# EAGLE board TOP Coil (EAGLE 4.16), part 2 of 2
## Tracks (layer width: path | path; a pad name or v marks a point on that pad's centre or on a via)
+1.2V  (via drill 0.51)
  Top 0.178: v160.66,116.84 160.34,116.52 159.54,116.52 IC9.37 158.27,116.52 155.1,116.52 154.15,117.47 152.72,117.47 | v156.84,113.03 156.69,113.35 156.69,114.14 IC9.35 | IC9.26 152.24,115.41 152.24,115.89 v152.4,116.39 152.56,116.52 152.56,117.32 152.72,117.47 | 157.53,122.98 156.21,124.3 156.21,126.68 156.37,126.84 157.16,126.84 v157.48,127 157.16,127.32 157.16,128.59 v157.35,128.91 157.8,129.06 158.27,129.06 IC9.62 | IC16.2 v107.31,95.09 107.31,96.2 107.31,96.21 | v140.21,137.35 140.18,136.84 140.18,136.53 IC9.107 | IC9.81 153.19,135.1 153.19,134.3 v153.03,133.99 152.72,133.67 152.72,132.87 145.89,126.05 144.15,126.05 | v139.7,126.36 139.38,126.52 138.59,126.52 IC9.124 | 141.1,126.05 141.1,123.79 140.81,123.51 140.02,123.51 v139.7,123.19 139.38,123.03 138.59,123.03 IC9.131 137.32,123.03 136.05,123.03 127,113.98 v127,113.35 | 141.1,126.05 144.15,126.05 | 141.1,126.05 141.1,126.11 | 141.1,126.11 141.1,132.78 139.89,133.99 138.59,133.99 IC9.109 136.46,134.06 v136.02,134.49 | 144.15,126.05 152.72,117.47 | v157.23,122.56 157.73,123.06 158.87,123.06 158.88,123.06 IC9.50 | v141.43,126.34 141.2,126.11 141.1,126.11
  Bottom 0.178: v160.66,116.84 159.7,116.84 C58.2 159.26,116.71 159.26,114.47 C52.2 156.69,113.98 156.69,113.35 v156.84,113.03 | C54.2 152.4,115.57 v152.4,116.39 152.72,116.52 152.72,119.03 157.19,123.51 | v157.35,128.91 158.12,128.91 C48.2 | 157.19,123.51 158.12,123.51 C51.2 157.86,123.06 v157.23,122.56 | 157.19,123.51 156.21,124.49 156.21,126.68 156.37,126.84 157.16,126.84 v157.48,127 | v140.21,137.35 C53.2 139.86,135.57 138.43,135.57 137.79,134.94 137.79,134.14 C50.2 136.56,134.49 v136.02,134.49 | v153.03,133.99 153.03,134.94 C49.2 | v139.7,123.19 138.75,123.19 C56.2 | C57.2 138.75,126.36 v139.7,126.36 141.48,126.36 v141.43,126.34 | v107.31,95.09 108.74,95.09 v127,113.35
  pour Top (isolate 0.203): 100.97,125.09 100.97,95.89 116.2,95.89 116.2,125.09
+3.3V  (via drill 0.51)
  Top 0.178: C3.1 IC1.27 124.14,34.45 124.94,34.45 128.59,38.1 128.59,62.55 132.4,66.36 132.4,69.37 132.56,69.53 133.35,69.53 C63.1 133.67,70.17 133.67,71.6 IC11.27 133.83,73.66 v133.83,75.41 | C64.1 IC12.27 v129.54,189.23 | C19.1 IC4.27 v119.22,157.48 119.54,157.8 v122.24,160.5 | SW1.10 SW1.9 SW1.8 SW1.7 | SW1.7 SW1.6 | IC9.66 158.27,130.97 157.67,130.97 v157.29,130.81 157.04,130.49 156.37,130.49 155.26,129.38 155.26,121.44 156.05,120.65 157.16,120.65 157.42,120.84 v157.29,120.71 157.8,121.13 158.27,121.13 IC9.46 159.54,121.13 162.37,121.13 162.53,121.28 162.53,124.94 162.37,125.09 159.54,125.09 IC9.54 158.27,125.09 v157.29,125.09 | IC9.77 155.26,135.1 155.26,134.3 v154.94,133.99 | v151.76,133.99 151.61,134.3 151.61,135.1 IC9.84 | v139.46,131.13 138.98,130.49 138.59,130.49 IC9.116 | IC9.102 142.72,135.1 142.72,134.81 v143.13,134.24 | v146.05,133.99 146.21,134.3 146.21,135.1 IC9.95 146.21,136.53 146.21,141.29 145.61,141.89 145.61,146.4 146.05,146.84 146.05,151.45 SW1.7 | v150.5,116.39 150.65,115.89 150.65,115.41 IC9.23 150.65,114.14 150.65,113.19 v147.96,110.49 | v153.67,116.39 153.67,115.41 IC9.29 | IC9.5 141.6,115.41 v141.6,116.84 141.6,117.32 139.38,119.54 138.59,119.54 IC9.138 | R54.2 92.87,87 92.87,88.42 92.55,88.42 IC15.2 92.08,96.2 92.08,96.21 | v139.7,125.09 138.59,125.09 IC9.127 | v99.69,96.68 98.9,96.68 C85.2
  Bottom 0.178: v129.54,189.23 129.54,178.44 119.22,168.12 v119.22,157.48 | v157.29,130.81 158.12,130.81 C44.2 158.12,131.44 158.12,133.83 156.37,135.57 | R35.1B 154.46,138.75 154.46,139.06 R35.2B 154.43,139.32 155.92,139.32 156.53,138.72 156.53,135.73 156.37,135.57 | 156.37,135.57 155.57,135.57 C43.2 154.94,134.94 v154.94,133.99 154.62,133.67 154.62,132.87 154.46,132.72 152.08,132.72 151.92,132.87 151.92,133.67 v151.76,133.99 151.76,134.94 C42.2 151.29,135.41 146.53,135.41 C33.2 | C40.2 138.75,130.81 v139.46,131.13 139.81,130.49 142.88,130.49 143.6,131.22 143.6,133.92 v143.13,134.24 142.88,134.94 C41.2 143.03,135.41 145.73,135.41 C33.2 | v146.05,133.99 146.05,134.94 C33.2 | v150.5,116.39 150.5,115.57 C38.2 150.97,114.62 151.29,114.3 152.88,114.3 153.19,114.62 C36.2 v153.67,116.39 153.99,116.52 153.99,117.32 157.07,120.4 157.07,120.49 v157.29,120.71 158.12,121.28 C34.2 | v157.29,125.09 C45.2 | 147.64,110.17 142.88,114.94 142.08,114.94 C39.2 141.6,115.57 v141.6,116.84 141.45,117.16 141.45,119.86 140.65,120.65 | 147.64,110.17 148.91,108.9 148.91,106.68 R31.2B 148.99,105.81 148.18,105 148.19,105 R31.3A | 147.64,110.17 v147.96,110.49 | C46.2 138.75,125.09 v139.7,125.09 140.02,124.78 140.81,124.78 140.97,124.62 140.97,120.97 140.65,120.65 | 140.65,120.65 139.86,119.86 138.75,119.86 C47.2 137.79,119.22 137.79,118.11 137.64,117.95 137,117.95 C35.1 136.05,117.63 135.1,117.63 IC8.4 132.87,116.68 132.24,116.68 131.13,115.57 | v99.69,96.68 109.22,96.68 128.11,115.57 131.13,115.57 | 131.13,115.57 131.13,112.87 135.89,108.11 136.84,108.11 IC7.3 138.75,107.79 140.02,107.79 141.13,106.68 IC7.7 IC7.8 143.13,105.41 143.99,104.55
  Bottom 0.178: v122.24,160.5 127.16,160.5 127.95,161.29 129.54,161.29 137.79,153.03 138.43,153.03 SW1.10 | v133.83,75.41 140.97,82.55 140.97,93.82 145.41,98.27 J3.4 144.78,100.01 143.99,100.81 143.99,104.55 | C37.1 145.16,104.52 144.02,104.52 143.99,104.55
  pour Top (isolate 0.203): 98.42,95.89 98.42,125.09 83.19,125.09 83.19,95.89
+5V  (via drill 0.51)
  Top 0.178: R48.2 120.65,14.45 120.65,15.72 Q6.3 | IC1.24 C1.2 120.97,37.62 120.97,36.99 119.54,35.56 118.9,35.56 | 118.9,35.56 115.73,32.38 115.73,24.29 | 115.73,24.29 115.73,23.65 115.57,23.5 R44.2 | 115.73,24.29 120.65,19.37 120.65,17.3 Q6.3 | AUD1.+ 143.67,6.35 136.37,6.35 126.84,15.88 121.92,15.88 Q6.3 | C74.2 IC14.5 | C61.2 IC12.24 133.35,189.39 130.02,186.06 119.86,186.06 C74.2 | C17.2 v115.73,161.29 IC4.24 | IC5.8 C22.2 100.81,177.16 v102.08,177.16 | v106.05,173.51 118.27,185.74 118.9,185.74 C74.2 | C55.1 160.66,91.6 IC10.14 160.34,88.58 160.34,87.31 155.57,82.55 138.59,82.55 130.49,74.45 130.02,74.45 | C59.2 129.86,70.17 129.86,71.6 IC11.24 130.02,73.66 130.02,74.45 | C77.2 64.29,111.12 PWR1.+VIN 63.82,110.49 63.82,107.16 F1.2A 65.88,105.89 66.67,105.89 68.26,104.3 69.22,104.3 C76.+ 71.75,102.87 v74.77,102.87 | v99.54,56.67 99.54,55.88 C6.2 | v101.6,56.99 IC2.8 | IC15.3 95.09,90.33 96.68,90.33 C78.2 97.63,90.17 98.27,90.17 100.97,87.47 109.22,87.47 109.38,87.63 109.38,88.42 IC16.3 110.33,88.74 111.92,88.74 C79.2 112.55,88.27 112.55,85.09 123.19,74.45 130.02,74.45 | IC15.3 94.61,72.23 94.77,72.07 95.41,72.07 C72.2 IC13.5 95.89,68.74 v95.73,68.58 | v93.34,90.49 94.14,90.49 IC15.3 | 118.9,35.56 118.9,36.35 108.9,46.35 106.52,46.35 v105.41,47.47
  Bottom 0.178: v115.73,161.29 115.73,162.88 113.82,164.78 | 113.82,164.78 108.27,170.34 108.27,170.97 105.89,173.35 | v102.08,177.16 105.89,173.35 | 105.89,173.35 v106.05,173.51 | v99.54,56.67 101.28,56.67 v101.6,56.99 | v95.73,68.58 94.77,67.63 94.77,65.72 97.95,62.55 97.95,58.9 99.22,57.63 99.22,56.99 v99.54,56.67 | 80.64,102.87 80.96,102.87 v93.34,90.49 | 80.64,102.87 v74.77,102.87 | 113.82,164.78 80.64,131.6 80.64,102.87 | v105.41,47.47 105.41,50.8 99.85,56.36 v99.54,56.67
+7V  (via drill 0.51)
  Top 0.178: C9.1 IC3.7 | v90.33,41.91 90.33,41.75 89.53,41.75 R9.2 | v97.79,43.02 97.95,43.18 98.58,43.18 C9.1 | C8.+ 103.98,43.02 99.54,43.02 C9.1 | C87.2 101.76,133.99 101.76,135.41 100.17,137 100.01,137 99.54,137.48 99.54,138.27 C92.+ 99.54,139.86 99.54,150.18 104.62,155.26 104.62,158.43 103.5,159.54 103.5,161.93 C24.+ 102.08,164.31 v100.17,164.31 | 106.84,137.79 106.84,133.51 IC17.2 107.31,131.13 107.31,130.33 109.38,130.33 109.38,129.54 R55.2 109.7,128.27 v109.7,127.48 | IC6.7 C25.1 95.73,165.74 96.04,165.74 96.04,168.28 | 96.04,168.28 96.04,170.02 96.52,170.5 96.52,177.32 93.82,177.32 93.03,176.53 91.28,176.53 R23.2 | 96.04,168.28 v96.2,168.28
  Bottom 0.178: v90.33,41.91 96.68,41.91 v97.79,43.02 97.47,43.34 97.47,62.39 93.98,65.88 93.98,90.01 97.47,93.5 97.47,115.25 v109.7,127.48 | v100.17,164.31 99.54,164.31 96.2,167.64 v96.2,168.28
  pour Top (isolate 0.203): 100.33,147.96 100.33,137.79 113.03,137.79 113.03,147.96
-5V  (via drill 0.51)
  Top 0.178: IC14.2 118.43,191.93 C71.2 117.79,192.88 v117.79,193.68 | C23.2 98.27,177.8 98.9,177.8 99.22,178.12 99.22,178.75 99.69,179.23 v99.69,182.72 99.54,182.88 97.95,182.88 97.79,182.72 IC5.6 | 104.46,57.31 106.84,57.31 107.47,56.67 107.47,55.88 C7.2 | 104.46,57.31 104.14,56.99 IC2.6 | C89.1 77.31,81.12 78.26,81.12 R57.1 IC19.5 v78.74,78.11 | C84.2 81.12,73.03 82.55,73.03 C94.- | C94.- 84.93,71.6 84.93,70.8 90.49,65.25 96.04,65.25 C70.2 96.84,65.41 IC13.2 96.84,68.42 97,68.58 99.85,68.58 104.46,63.98 104.46,57.31 | v82.87,73.98 82.87,73.18 C94.-
  Bottom 0.178: v117.79,193.68 110.65,193.68 v99.69,182.72 99.38,182.4 96.04,182.4 86.84,173.2 86.84,160.97 85.88,160.02 85.88,158.43 86.84,157.48 86.84,138.43 73.98,125.57 73.98,82.87 v78.74,78.11 v82.87,73.98
-7V  (via drill 0.51)
  Top 0.178: R10.1 87,38.58 87,39.21 v87.47,39.69 97,39.69 97.31,39.37 100.33,39.37 101.6,38.1 IC3.4 C11.2 102.08,33.66 C10.- | C83.2 91.92,133.99 93.34,133.99 C93.- 93.5,135.41 93.5,136.21 92.55,137.16 92.55,137.95 91.92,138.59 89.69,138.59 89.69,139.38 IC18.5 R56.1 89.06,141.45 88.11,141.45 C88.1 87.15,141.92 86.52,141.92 | IC6.4 C27.2 97.31,154.94 96.68,154.94 86.36,144.62 86.36,142.08 86.52,141.92 | v89.53,173.2 88.27,173.2 R24.1 | IC6.4 v97.79,159.38 | C26.- 97.95,156.84 IC6.4 | 86.52,141.92 v86.04,141.45
  Bottom 0.178: v89.53,173.2 97.79,164.94 v97.79,159.38 | v87.47,39.69 87.47,42.55 73.5,56.52 73.5,128.91 v86.04,141.45
/DISABLE  (via drill 0.51)
  Top 0.178: v127.32,143.19 134.78,143.19 Q5.3 | v108.9,158.75 108.58,159.07 v105.09,159.07 | v93.98,160.81 IC6.8 | v81.44,110.17 75.56,104.3 75.56,74.61 91.92,58.26 91.92,47.15 96.84,42.23 97.63,42.23 IC3.8
  Bottom 0.178: v127.32,143.19 124.46,143.19 121.13,146.53 | v108.9,158.75 121.13,146.53 | v105.09,159.07 99.22,159.07 98.27,158.12 94.14,158.12 93.34,158.91 93.34,160.18 v93.98,160.81 | v81.44,110.17 104.78,133.51 109.38,133.51 116.68,140.81 116.68,142.08 121.13,146.53 | 121.13,146.53
AGND  (via drill 0.51, 0.71)
  Top 3.81: 17.78,49.02 17.78,55.12 | 24.13,68.71 24.13,74.8 | 24.13,140.46 24.13,146.56 | 17.78,185.55 17.78,191.64
  Bottom 0.178: C50.1 139.27,133.73 139.94,134.41 C53.1
  Bottom 3.81: 17.78,49.02 17.78,55.12 | 24.13,68.71 24.13,74.8 | 24.13,140.46 24.13,146.56 | 17.78,185.55 17.78,191.64
  other vias: 109.86,156.21 110.49,158.88 112.39,158.88 95.63,172.21 97.54,172.21 131.95,194.31 130.94,196.34 171.45,86.23 163.58,93.47 160.27,93.73 147.96,97.16 147.96,86.61 154.69,87.63 155.07,84.96 130.97,110.49 136.37,114.14 143.51,112.39 141.86,131.44 142.62,139.95 149.48,113.28 152.78,112.01 161.67,123.06 161.54,126.24 160.78,129.03 160.91,132.46 153.24,137.36 150.16,137.34 144.48,137.39 158.34,115.37 135.25,124.84 135,119.76 76.96,76.83 86.49,76.83 132.08,63.5 130.18,66.04 131.7,120.02 134.37,122.94 99.19,87 100.46,89.53 155.65,138.38 80.77,22.86 79.5,36.83 77.6,45.72 81.41,59.69 94.11,60.96 111.25,38.1 108.71,60.96 108.08,72.39 92.84,129.54 78.23,120.02 64.9,148.59 67.44,163.19 82.68,180.97 90.3,193.68 163.32,173.99 170.94,122.56 137.29,94.61 143,56.52 157.61,52.07 108.08,150.5 113.79,128.91 99.82,120.02 99.82,106.68 151.26,124.46 94.74,149.22 92.2,154.31 90.3,161.93 109.98,163.83 131.57,170.81 84.58,137.79 116.33,46.99 99.19,50.16 125.22,66.04
  pour Top (isolate 0.203, rank 2): 6.35,0 17.78,0 17.78,7.62 118.11,7.62 118.11,0 171.45,0 arc-242 177.8,6.35 177.8,194.31 arc-242 171.45,200.66 6.35,200.66 arc-242 0,194.31 0,6.35 arc-242
  pour Bottom (isolate 0.203, rank 2): 0,0 0,200.66 177.8,200.66 177.8,0
COM-X  (via drill 0.51)
  Top 0.178: C60.1 120.17,67.79 121.76,67.79 R36.1 122.87,67.79 124.78,67.79 | 124.78,67.79 127.64,67.79 C65.1 128.27,67.47 v128.27,66.67 | IC11.16 119.54,71.6 119.54,70.8 118.75,70.8 118.59,70.64 118.59,68.26 119.38,68.26 C60.1 | 124.78,67.79 124.78,71.6 IC11.20 | v132.4,70.8 132.4,71.6 IC11.26 | C2.1 119.7,42.07 119.7,41.75 122.24,41.75 IC1.21 | 125.09,41.75 125.09,35.88 124.94,35.72 124.14,35.72 IC1.26 | 125.09,41.75 124.94,41.91 IC1.21 | IC1.21 IC1.20 | 125.09,41.75 125.09,47.94 124.94,48.1 124.14,48.1 IC1.16 122.24,48.42 122.24,48.58 121.13,48.58 C4.1 121.13,49.53 121.13,52.86 R2.CW 121.6,54.13 121.6,56.04 119.7,57.94 | 119.7,57.94 119.7,67.47 C60.1 | R38.1 C67.1 100.33,53.34 | 100.33,53.34 101.44,53.34 v102.87,51.91 | 100.33,53.34 99.54,53.34 C6.1 | v102.87,51.91 IC2.2 | v100.33,38.26 IC3.3 v100.33,34.45 | v102.87,51.91 103.19,52.07 105.09,52.07 105.25,51.91 105.25,51.12 IC2.4 R3.1 107.16,50.8 107.16,51.59 C5.1 107.47,52.55 107.47,53.34 C7.1 108.43,53.98 109.06,53.98 113.03,57.94 119.7,57.94
  Bottom 0.178: v128.27,66.67 v132.4,70.8 | v100.33,38.26 100.33,43.34 98.74,44.93 98.74,47.78 v102.87,51.91 | v100.33,34.45 93.98,28.1 85.72,28.1 84.77,29.05 56.83,29.05 36.51,49.37 26.83,49.37 R14.2B
COM-Y  (via drill 0.51)
  Top 0.178: 138.43,194.94 137.64,194.94 C62.1 136.68,195.1 135.73,195.1 C66.1 135.1,195.58 135.1,196.37 134.94,196.53 132.56,196.53 130.97,194.94 130.97,192.09 IC12.26 130.81,189.39 129.22,187.8 125.09,187.8 C68.1 R39.1 121.92,187.17 v120.49,187.17 | 138.43,194.94 140.49,194.94 R37.1 | 138.43,194.94 IC12.20 138.43,189.39 138.59,189.23 143.19,189.23 143.35,189.39 143.35,190.18 IC12.16 | C20.1 114.78,165.1 IC4.21 | 119.38,164.94 119.38,159.07 119.22,158.91 118.43,158.91 IC4.26 | 119.38,164.94 119.22,165.1 IC4.21 | IC4.21 IC4.20 | 119.38,164.94 119.38,171.13 119.22,171.29 118.43,171.29 IC4.16 114.78,171.45 C18.1 113.82,172.09 v113.82,172.88 | C21.1 104.93,188.12 103.5,188.12 R17.1 99.22,187.96 | 99.22,187.96 99.06,187.8 IC5.2 99.22,185.1 99.22,184.31 100.81,182.72 101.12,182.72 106.36,177.48 | 99.22,187.96 96.84,187.96 96.68,187.8 96.68,187.01 IC5.4 96.36,185.26 37.78,185.26 37.15,185.9 26.83,185.9 R28.2B | 99.38,175.74 99.85,175.74 C22.1 100.81,176.05 104.93,176.05 106.36,177.48 | 99.38,175.74 98.27,175.74 C23.1 | 106.36,177.48 107.63,178.75 108.43,178.75 R16.CW | 99.38,175.74 99.38,161.77 98.42,160.81 98.11,160.81 96.68,159.38 96.68,158.43 IC6.3
  Bottom 0.178: v113.82,172.88 113.03,172.88 109.54,176.37 109.54,177.01 | 109.54,177.01 109.54,178.28 R16.CW | v120.49,187.17 119.7,187.17 109.54,177.01
DIS-IN  (via drill 0.51)
  Top 0.178: v140.65,119.54 140.23,119.54 138.71,121.06 IC9.135
  Bottom 0.178: v140.65,119.54 139.7,118.59 139.7,113.03 140.02,113.03 R30.2A
FREQ0  (via drill 0.51)
  Top 0.178: v141.6,134.14 142.4,133.35 143.35,133.35 144.15,134.14 144.15,135.1 IC9.99
  Bottom 0.178: R32.1B 142.08,146.84 139.06,146.84 SW1.1 139.06,142.72 141.6,140.18 v141.6,134.14
FREQ1
  Top 0.178: IC9.97 145.26,136.53 145.26,139.06 141.6,142.72 SW1.2
  Bottom 0.178: R32.2B 142.88,146.69 142.88,145.89 142.08,145.89 SW1.2
FREQ2
  Top 0.178: IC9.96 145.73,136.53 145.73,141.13 144.15,142.72 SW1.3
  Bottom 0.178: R32.3B 144.15,146.69 SW1.3
FREQ3
  Top 0.178: IC9.94 146.69,136.53 SW1.4
  Bottom 0.178: R32.4B 144.94,146.69 145.73,146.69 145.89,146.53 145.89,145.73 146.05,145.73 SW1.4
FREQ4
  Top 0.178: IC9.93 147.16,136.53 147.16,140.65 149.22,142.72 SW1.5
  Bottom 0.178: SW1.5 R29.2
GAIN0  (via drill 0.51)
  Top 0.178: v131.13,156.84 131.13,167.16 128.11,170.18 IC4.12 | v124.46,52.86 124.46,54.61 v120.49,58.58 | v118.43,60.64 115.73,63.34 v115.73,80.8 | v124.3,113.03 v124.3,109.54 | v130.33,46.99 IC1.12 | v131.44,128.91 131.57,128.91 134.11,126.36 134.11,124.08 | IC9.129 134.11,124.06 134.11,124.05 134.11,124.08 | v127.16,115.89 127.76,116.49 127.76,117.86 133.99,124.08 134.11,124.08
  Bottom 0.178: v131.44,128.91 131.44,156.53 v131.13,156.84 | v124.46,52.86 v130.33,46.99 | v118.43,60.64 v120.49,58.58 | v115.73,80.8 115.73,101.44 123.83,109.54 v124.3,109.54 | v127.16,115.89 v124.3,113.03
GAIN1  (via drill 0.51)
  Top 0.178: 131.44,130.18 128.11,133.51 v128.11,135.57 | 131.44,130.18 135,126.62 135,126.11 135.51,125.6 arc90 135.54,125.57 137.32,125.57 IC9.126 | v128.27,157 130.65,159.38 130.65,166.37 128.11,168.91 IC4.11 | v130.33,45.88 131.13,45.88 IC1.11 | v125.25,50.96 125.25,62.39 v120.81,66.83 | v123.83,122.4 v122.71,121.28 | v128.91,127.48 131.44,130.02 131.44,130.18 | 131.44,130.18
  Bottom 0.178: v128.11,135.57 128.11,142.24 128.59,142.72 128.59,156.69 v128.27,157 | v125.25,50.96 v130.33,45.88 | v120.81,66.83 120.81,74.45 98.9,96.36 98.9,97 108.27,106.36 111.44,106.36 122.71,117.63 v122.71,121.28 | v128.91,127.48 v123.83,122.4
GAIN2  (via drill 0.51)
  Top 0.178: v128.91,134.78 128.91,133.35 135.64,126.62 135.64,126.05 135.65,126.05 135.74,125.96 137.06,125.96 137.15,126.05 137.32,126.05 IC9.125 | v128.91,158.75 130.18,160.02 130.18,165.58 128.11,167.64 IC4.10 | v130.33,44.61 131.13,44.61 IC1.10 | v118.9,66.83 v118.9,63.66 | v123.83,128.43 v122.56,127.16 | v125.89,130.49 125.89,131.44 v127.48,133.03
  Bottom 0.178: v128.91,158.75 129.06,158.59 129.06,142.56 128.91,142.4 v128.91,134.78 128.91,134.46 v127.48,133.03 | v130.33,44.61 123.67,51.28 123.67,58.9 v118.9,63.66 | v118.9,66.83 118.9,75.72 98.42,96.2 98.42,108.11 117.47,127.16 v122.56,127.16 | v125.89,130.49 v123.83,128.43
GAIN3  (via drill 0.51)
  Top 0.178: v129.7,133.67 135.89,127.48 137.32,127.48 IC9.122 | v129.38,160.34 129.38,165.1 128.11,166.37 IC4.9 | v117.63,71.12 v117.63,63.66 | v129.7,43.18 IC1.9
  Bottom 0.178: v129.38,160.34 129.7,160.02 v129.7,133.67 128.11,132.08 127.16,132.08 126.68,132.56 126.68,137.32 123.51,140.49 122.87,140.49 122.4,140.02 122.4,133.19 97.95,108.74 97.95,96.04 117.63,76.36 v117.63,71.12 | v129.7,43.18 117.63,55.24 v117.63,63.66
GAIN4  (via drill 0.51)
  Top 0.178: v136.21,128.27 136.37,128.11 137.32,128.11 IC9.121 | v134.62,129.86 134.62,130.18 123.67,141.13 v123.67,153.67 | v128.27,160.5 128.27,164.94 128.11,165.1 IC4.8 | v129.38,41.27 129.86,41.75 131.13,41.75 IC1.8 | v120.02,54.13 v120.02,50.64 | v118.43,59.21 116.68,59.21 113.03,62.87 v113.03,83.5 | v113.67,88.11 113.67,87.95 113.03,87.31 113.03,86.68 113.51,86.2 114.14,86.2 120.33,92.39 v120.33,111.12 | v127,117.79 132.24,123.03 v132.24,125.41
  Bottom 0.178: v136.21,128.27 135.73,128.27 133.19,125.73 132.56,125.73 | 132.56,125.73 132.08,126.21 132.08,127.32 v134.62,129.86 | v123.67,153.67 123.67,155.89 v128.27,160.5 | v120.02,50.64 v129.38,41.27 | v120.02,54.13 121.13,55.24 121.13,56.52 v118.43,59.21 | v113.03,83.5 113.03,87.47 v113.67,88.11 | v127,117.79 v120.33,111.12 | v132.24,125.41 132.56,125.73
GAIN5  (via drill 0.51)
  Top 0.178: v139.38,128.21 138.59,128.59 IC9.120 | v127.32,122.56 v130.65,122.56 | v120.81,130.33 120.81,138.43 116.52,142.72 v116.05,142.72 | v116.05,150.5 v118.27,152.72 | v121.6,156.05 121.6,158.75 123.35,160.5 123.35,162.56 124.62,163.83 IC4.7 | v115.89,61.28 113.82,63.34 v113.82,82.71 | v113.82,87 119.54,92.71 v119.54,119.22 | v130.33,40.64 IC1.7
  Bottom 0.178: v139.38,128.21 137.64,128.59 136.84,127.79 136.84,127.48 135.57,127.48 135.59,127.48 135.58,127.48 134.94,126.84 v130.65,122.56 | v127.32,122.56 125.09,122.56 124.14,121.6 123.51,121.6 123.03,122.08 123.03,122.71 | 123.03,122.71 123.03,126.52 123.35,126.84 123.35,127.79 v120.81,130.33 | v116.05,142.72 v116.05,150.5 | v118.27,152.72 v121.6,156.05 | v130.33,40.64 130.33,41.43 118.59,53.18 118.59,53.66 118.43,53.82 118.11,53.82 118.11,54.13 117.79,54.13 117.79,54.45 117.47,54.45 117.47,54.77 117.32,54.77 117.32,54.93 115.89,56.36 v115.89,61.28 | v113.82,87 v113.82,82.71 | 123.03,122.71 v119.54,119.22
GAIN6  (via drill 0.51)
  Top 0.178: v135.41,129.06 137.32,129.06 IC9.119 | v132.87,126.52 131.29,126.52 v131.13,126.36 | v123.19,139.7 123.19,153.03 122.56,153.67 122.56,159.07 123.83,160.34 123.83,161.77 124.62,162.56 IC4.6 | v133.83,39.53 133.03,39.53 IC1.6 | v131.6,68.9 131.6,71.28 131.76,71.28 131.76,74.61 v131.92,74.77 | v122.71,116.52 v122.71,104.62
  Bottom 0.178: v132.87,126.52 v135.41,129.06 | v123.19,139.7 123.19,134.3 v131.13,126.36 130.81,126.05 130.81,124.94 122.71,116.84 v122.71,116.52 | v133.83,39.53 133.83,66.67 v131.6,68.9 | v131.92,74.77 131.44,74.77 126.84,79.38 126.84,85.41 128.59,87.15 128.59,98.74 v122.71,104.62
GAIN7  (via drill 0.51)
  Top 0.178: IC9.118 137.32,129.54 136.08,129.54 124.46,141.16 124.46,153.99 123.03,155.42 123.03,158.91 124.62,160.5 v124.62,161.29 IC4.5 | v141.13,164.31 v144.78,164.31 | v135.1,38.1 IC1.5
  Bottom 0.178: v135.1,38.1 137.32,38.1 174.78,75.56 174.78,136.05 146.53,164.31 v144.78,164.31 | v141.13,164.31 141.13,163.19 139.7,161.77 125.09,161.77 v124.62,161.29
GAIN8  (via drill 0.51)
  Top 0.178: IC9.115 137.32,131.13 135.73,131.13 v125.25,141.6 124.94,141.92 124.94,154.15 123.51,155.57 123.51,158.75 124.62,159.86 125.41,159.86 IC4.4 | v129.38,38.58 129.38,37.94 130.33,36.99 131.13,36.99 IC1.4 | v116.52,80.01 v116.52,63.66 | v118.27,102.87 118.27,136.53 v119.86,138.11
  Bottom 0.178: v129.38,38.58 129.06,38.58 115.09,52.55 115.09,62.23 v116.52,63.66 | v116.52,80.01 116.52,101.12 v118.27,102.87 | v119.86,138.11 123.35,141.6 v125.25,141.6
GAIN9  (via drill 0.51)
  Top 0.178: 124.14,158.27 124.62,158.75 IC4.3 | 124.14,158.27 123.98,158.12 123.98,155.73 126.05,153.67 126.05,141.45 135.89,131.6 137.32,131.6 IC9.114 | v149.22,51.12 133.83,35.72 133.03,35.72 IC1.3 | v140.34,163.51 v145.57,163.51 | 124.14,158.27 v124.62,158.27 | 124.14,158.27
  Bottom 0.178: v149.22,51.12 149.22,53.18 174.31,78.26 174.31,135.89 146.69,163.51 v145.57,163.51 | v140.34,163.51 124.14,163.51 121.44,160.81 121.44,160.18 123.35,158.27 v124.62,158.27
GAIN10  (via drill 0.51)
  Top 0.178: 126.52,149.86 126.52,153.83 124.46,155.89 124.46,157.32 124.62,157.48 IC4.2 | 126.52,149.86 126.52,141.6 136.05,132.08 137.32,132.08 IC9.113 | v133.83,34.45 133.03,34.45 IC1.2 | v146.84,162.24 146.53,162.24 146.05,162.72 139.38,162.72 126.52,149.86
  Bottom 0.178: v133.83,34.45 133.83,38.42 173.83,78.42 173.83,135.25 v146.84,162.24
GAIN11  (via drill 0.51)
  Top 0.178: v127.32,142.08 127.32,141.45 136.21,132.56 137.32,132.56 IC9.112 | v127.79,152.24 127,153.03 127,156.05 IC4.1 | v126.05,32.86 131.13,32.86 IC1.1 | v114.62,81.92 v114.62,63.66 | v114.62,88.9 118.11,92.39 118.11,99.69 117.47,100.33 v117.47,140.65
  Bottom 0.178: v127.79,152.24 128.11,151.92 128.11,142.88 v127.32,142.08 127,142.4 124.62,142.4 123.51,143.51 118.75,143.51 117.47,142.24 v117.47,140.65 | v126.05,32.86 125.41,32.23 124.62,32.23 114.62,42.23 v114.62,63.66 | v114.62,88.9 v114.62,81.92
GAINX  (via drill 0.51)
  Top 0.178: v127.79,87.47 127.79,114.14 136.21,122.56 IC9.132 | v124.94,33.02 IC1.28
  Bottom 0.178: v127.79,87.47 120.49,80.17 120.49,78.58 127.95,71.12 127.95,67.47 127.48,66.99 127.48,50.96 131.13,47.31 131.13,39.21 v124.94,33.02
GAINY  (via drill 0.51)
  Top 0.178: v136.53,121.76 136.53,122.08 137.32,122.08 IC9.133 | v120.33,114.14 120.33,129.7 v119.06,130.97 | v119.06,142.72 119.06,154.46 118.27,155.26 118.27,156.05 IC4.28
  Bottom 0.178: v136.53,121.76 129.06,121.76 121.44,114.14 v120.33,114.14 | v119.06,130.97 v119.06,142.72
N$1  (via drill 0.51)
  Top 0.178: v97.95,38.58 97.95,37.15 IC3.1 | v95.41,41.12 95.41,43.02 90.49,47.94 90.49,50.64 R6.CCW
  Bottom 0.178: v97.95,38.58 v95.41,41.12
N$2  (via drill 0.51)
  Top 0.178: v102.55,40.32 101.76,40.32 IC3.5
  Bottom 0.178: v102.55,40.32 102.55,38.73 100.81,36.99 93.66,36.99 85.41,45.24 85.41,50.64 R6.CW
N$3
  Top 0.178: C16.1 75.09,33.66 43.02,33.66 41.27,35.4 40.48,35.4 38.73,35.81 Q1.3 | 37.08,81.53 Q2.3 | J1.1 7.46,41.27 7.49,41.27
  Top 3.81: 7.49,41.27 24.13,41.27 | 24.13,41.27 29.59,35.81 38.73,35.81 | 24.13,41.27 31.75,48.9 31.75,76.2 37.08,81.53 38.73,81.53
  Bottom 0.178: J1.1 11.59,41.27
  Bottom 3.81: 7.49,41.27 11.59,41.27 24.13,41.27 29.59,35.81 38.73,35.81
N$4
  Top 0.178: J1.2 7.46,36.67 7.49,36.7
  Top 3.81: 7.49,36.7 R14.1A
  Bottom 3.81: R14.1A 7.49,36.7
N$5  (via drill 0.51)
  Top 0.178: R8.1 89.53,38.26 90.96,38.26 C13.1 91.92,38.73 v93.03,38.73 | R7.1 86.68,40.8 86.68,40.48 89.85,40.48 89.85,40.64 90.96,40.64 C12.1 91.92,40.96 92.55,40.96 v93.03,40.48 | v101.28,39.53 101.28,39.85 100.49,39.85 100.49,40.32 IC3.6
  Bottom 0.178: v93.03,40.48 v93.03,38.73 93.34,38.42 97,38.42 97.95,37.47 100.65,37.47 101.12,37.94 101.12,39.21 v101.28,39.53 101.28,42.23 102.23,43.18 X-DRV.TP
N$6  (via drill 0.51)
  Top 0.178: C12.2 90.96,43.02 89.53,43.02 R9.1 R7.2 85.72,42.7 v84.93,42.7 84.45,42.23 40.32,42.23 Q1.1 | R11.CW 84.45,27.94 84.45,28.73 84.93,29.21 85.72,29.21 R11.W
  Bottom 0.178: v84.93,42.7 84.93,33.66 86.04,32.54 86.04,30.64 R11.W
N$7  (via drill 0.51)
  Top 0.178: C13.2 90.96,36.35 89.53,36.35 R8.2 R10.2 85.72,36.35 85.25,36.35 85.25,37.62 84.45,37.62 R12.1 83.5,38.58 83.5,39.21 v83.34,39.37
  Bottom 0.178: v83.34,39.37 83.34,44.93 40.96,87.31 40.32,87.31 Q2.1
N$8
  Top 0.178: R13.1 75.09,29.21 53.82,29.21 47.31,22.7 29.21,22.7 27.62,24.29 26.83,24.29 R14.1B
N$9
  Top 0.178: C16.2 R13.2 77.95,30.48 84.61,30.48 86.68,32.54 99.06,32.54 | 99.06,32.54 100.81,30.8 104.62,30.8 105.89,32.07 105.89,36.99 R4.2 | 99.06,32.54 IC3.2
N$10  (via drill 0.51)
  Top 0.178: v106.2,40.64 106.05,40.48 106.05,39.85 R4.1 | IC2.5 v105.41,53.18 105.09,53.34 103.19,53.34 103.03,53.5 103.03,54.29 IC2.7
  Bottom 0.178: v106.2,40.64 106.2,52.39 v105.41,53.18
N$11  (via drill 0.51)
  Top 0.178: C29.1 82.39,173.2 84.45,173.2 R22.1 | R22.1 85.41,172.88 85.41,172.56 88.9,172.56 89.69,171.77 90.33,171.77 C28.1 91.28,170.81 91.92,170.81 93.98,168.75 93.98,166.85 91.6,166.85 Y-DRV.TP | R21.1 84.77,175.26 84.77,173.83 R22.1 | v96.52,164.47 IC6.6
  Bottom 0.178: v96.52,164.47 93.98,167 Y-DRV.TP
N$12  (via drill 0.51)
  Top 0.178: 89.06,174.62 89.85,174.62 90.33,174.15 90.33,173.35 C28.2 | 89.06,174.62 89.06,175.26 R23.1 R21.2 | v89.06,174.31 89.06,174.62 | R25.W 87,158.75 87,157.96 86.52,157.48 85.72,157.48 R25.CW
  Bottom 0.178: v89.06,174.31 89.06,173.83 87.31,172.09 87.31,160.18 R25.W | Q3.1 40.32,133.67 60.64,133.67 83.5,156.53 84.3,156.53 R25.CW
N$13
  Top 0.178: R22.2 84.45,171.29 82.39,171.29 C29.2 81.44,171.45 80.8,171.45 73.5,178.75 40.32,178.75 Q4.1 | R22.2 R26.1 | R22.2 R24.2
N$14
  Top 0.178: Q3.3 38.73,127.25 | C32.1 75.72,153.03 62.07,153.03 42.55,172.56 40.48,172.56 38.61,172.97 Q4.3 | 6.99,178.91 J2.1 6.99,178.82
  Top 3.81: 6.99,178.82 14.48,178.82 20.32,172.97 31.75,172.97 | 31.75,172.97 38.61,172.97 | 31.75,172.97 31.75,132.08 36.58,127.25 38.73,127.25 | 31.75,172.97 31.75,173.35
  Bottom 0.178: 10.79,178.82 10.79,178.91 J2.1 | 37.47,127.51 37.47,127.64 Q3.3
  Bottom 3.81: 6.99,178.82 10.79,178.82 14.48,178.82 20.32,172.97 38.61,172.97 | 31.75,173.35 31.75,132.08 36.32,127.51 37.47,127.51 38.73,127.51
N$15
  Top 0.178: J2.2 6.99,174.24 6.99,174.31
  Top 3.81: 6.99,174.24 R28.1A
  Bottom 3.81: R28.1A 6.99,174.24
N$16
  Top 0.178: R27.1 76.68,155.57 76.68,154.15 76.99,153.83 76.99,150.97 68.42,142.4 60.33,142.4 42.55,124.62 35.56,124.62 27.78,132.4 27.78,158.43 26.51,159.7 26.51,160.5 R28.1B
N$17
  Top 0.178: 78.11,154.78 C32.2 | 78.11,154.78 R27.2 | 92.87,160.81 92.87,163.83 94.14,165.1 94.46,165.1 94.46,168.43 94.61,168.59 94.61,176.05 R18.2 | 92.87,160.81 93.66,160.02 94.46,160.02 95.25,159.23 IC6.2 | 78.11,154.78 86.84,154.78 92.87,160.81
N$18
  Top 0.178: 96.52,179.07 96.52,178.91 95.89,178.91 R18.1 | 96.52,179.07 IC5.5 | 96.52,179.07 98.74,179.07 98.9,179.23 98.9,180.02 IC5.7
N$19
  Top 0.178: C18.2 114.78,170.18 IC4.17
N$20
  Top 0.178: C20.2 114.78,163.19 115.41,163.19 115.73,162.88 115.73,162.56 IC4.23
N$21
  Top 0.178: R15.2 117.47,176.69 116.52,176.69 113.03,173.2 113.03,169.23 113.67,168.59 115.41,168.59 115.73,168.91 IC4.18
N$22
  Top 0.178: R15.1 117.47,179.23 115.09,179.23 R16.CCW 113.67,178.44 112.87,178.44 112.39,177.96 112.39,177.16 R16.W
N$23  (via drill 0.51)
  Top 0.178: C21.2 104.93,186.21 103.5,186.21 R17.2 | v115.73,163.99 116.52,163.99 IC4.22 | v103.19,182.09 103.19,185.58 R17.2 | R17.2 IC5.1
  Bottom 0.178: v115.73,163.99 115.73,169.54 v103.19,182.09
N$24
  Top 0.178: R26.2 85.25,166.53 85.25,162.72 R25.CCW
N$25  (via drill 0.51)
  Top 0.178: v94.14,159.23 94.14,158.43 IC6.1
  Bottom 0.178: v94.14,159.23 96.84,159.23 97.47,158.59 98.11,158.59 106.36,166.85 106.36,169.39 R20.CCW
N$26  (via drill 0.51)
  Top 0.178: v98.58,166.37 97.95,165.74 97.95,163.51 IC6.5
  Bottom 0.178: v98.58,166.37 98.58,169.7 97.79,170.5 97.79,171.13 98.27,171.61 98.9,171.61 100.01,170.5 100.81,170.5 R20.CW
N$27  (via drill 0.51)
  Top 0.178: C5.2 109.06,51.59 109.06,50.8 R3.2 109.7,49.53 110.65,49.53 111.76,48.42 | 111.76,48.42 117.79,42.39 117.79,41.91 119.06,40.64 IC1.22 | v99.54,58.42 97.79,56.67 97.79,53.02 99.69,51.12 101.44,51.12 IC2.1 | v110.65,47.31 111.76,48.42
  Bottom 0.178: v99.54,58.42 101.28,58.42 109.86,49.85 109.86,48.1 v110.65,47.31
N$28
  Top 0.178: C2.2 121.28,43.02 121.28,43.66 121.44,43.81 124.62,43.81 124.62,46.83 124.14,46.83 IC1.17
N$29  (via drill 0.51)
  Top 0.178: v98.58,170.81 98.42,170.66 98.42,170.02 R19.2
  Bottom 0.178: v98.58,170.81 101.44,167.96 103.35,167.96 R20.W
N$30
  Top 0.178: -MCOM.TP 9.05,74.61 13.81,74.61 14.29,74.14 15.08,74.14 R46.2B
N$31
  Top 0.178: -MON.TP 9.05,94.3 13.81,94.3 14.29,94.77 15.08,94.77 R46.1B
N$32
  Top 0.178: +MON.TP 9.05,120.97 13.81,120.97 14.29,120.49 15.08,120.49 R45.2B
N$33
  Top 0.178: +MCOM.TP 9.05,140.02 13.18,140.02 14.29,141.13 15.08,141.13 R45.1B
N$34
  Top 0.178: J7.2 6.99,105.66 6.99,105.73
  Top 3.81: 6.99,105.66 19.05,105.66 24.13,100.58 R46.1A
  Bottom 3.81: 6.99,105.66 19.05,105.66 24.13,100.58 R46.1A
N$35
  Top 0.178: 6.99,110.33 J7.1 6.99,110.24
  Top 3.81: 6.99,110.24 19.05,110.24 24.13,115.32 R45.2A
  Bottom 3.81: 6.99,110.24 19.05,110.24 24.13,115.32 R45.2A
N$36
  Top 0.178: R12.2 83.98,35.72 83.98,33.18 R11.CCW
N$37
  Top 0.178: R5.2 88.42,46.35 88.42,48.42 R6.W
N$38
  Top 0.178: +5V_IN.TP F1.1A
N$39
  Top 0.178: R51.1 66.04,138.91 PWR1.TRM
N$40  (via drill 0.51)
  Top 0.178: C80.2 111.28,132.87 110.17,132.87 IC17.3 109.06,133.51 v109.06,134.3 | R51.2 63.98,140.34 63.98,138.91 PWR1.+VOUT 63.98,135.89 63.98,135.1 66.04,133.03 v83.19,133.03
  Bottom 0.178: v109.06,134.3 84.45,134.3 v83.19,133.03
N$41
  Top 0.178: R54.1 R52.2 IC15.1
N$42
  Top 0.178: 129.7,22.38 129.54,22.23 129.54,18.89 130.18,18.89 R50.2 | 129.7,22.38 130.49,22.38 Q7.1 | 129.7,22.38 129.7,23.18 128.43,24.45 127,24.45 R49.1
N$43  (via drill 0.51)
  Top 0.178: v119.38,47.15 120.17,47.15 C4.2 | v121.44,39.37 IC1.23
  Bottom 0.178: v119.38,47.15 119.38,41.43 v121.44,39.37
N$44
  Top 0.178: IC9.14 146.21,114.14 146.21,110.65 140.34,104.78 J3.7
  Bottom 0.178: IC7.2 138.75,106.52 139.54,106.52 140.34,105.73 J3.7
N$45
  Top 0.178: IC19.4 R57.2 R59.1
N$46
  Top 0.178: R55.1 R53.2 105.57,129.54 105.57,130.33 105.41,130.49 104.93,130.49 104.93,131.13 IC17.1
N$47
  Top 0.178: IC18.4 R56.2 R58.1
N$48  (via drill 0.51)
  Top 0.178: 146.69,108.97 146.69,114.14 IC9.15 | 150.02,103.63 150.02,103.03 149.54,102.55 148.59,102.55 J3.1 | 150.02,103.63 150.02,103.66 | 146.69,108.97 145.54,108.97 v144.62,107.95 | 150.02,103.63 150.01,103.63 150.01,105.64 146.69,108.97
  Bottom 0.178: v144.62,107.95 IC7.6
N$49  (via drill 0.51)
  Top 0.178: 137.48,109.22 137.48,102.87 J3.9 | 137.48,109.22 137.48,110.65 139.54,112.71 139.54,114.14 IC9.1 | 137.48,109.22 v135.89,109.22
  Bottom 0.178: v135.89,109.22 135.89,108.74 136.05,108.58 139.54,108.58 140.02,109.06 141.92,109.06 IC7.5
N$50
  Top 0.178: R1.2 IC1.18
N$51
  Top 0.178: R1.1 118.27,46.35 118.27,50.64 117.16,51.75 117.16,52.55 R2.CCW 117.47,53.98 118.27,53.98 118.75,54.45 118.75,55.24 R2.W
N$52  (via drill 0.51)
  Top 0.178: IC9.2 140.18,114.14 140.18,112.71 137.95,110.49 137.95,104.78 v138.27,104.46 138.91,103.82 138.91,101.44 139.7,101.44 139.7,100.01 J3.8
  Bottom 0.178: v138.27,104.46 138.27,105.25 IC7.1
N$53  (via drill 0.51)
  Top 0.178: v153.67,141.92 150.81,139.06 150.81,137.95 150.82,137.92 152.16,136.58 IC9.83 | v157,145.26 157,144.94 162.08,139.86 162.08,139.7 162.4,139.38 162.4,130.02 v161.93,129.54
  Bottom 0.178: v157,145.26 v153.67,141.92 | v161.93,129.54 161.93,127.51 162.56,126.87 162.56,121.28 161.93,120.65 161.93,113.82 149.22,101.12 146.53,101.12 146.37,101.28 146.05,101.28 146.05,101.92 J3.3 146.74,103.56 146.74,105.39 147.8,105.39 148.19,105.77 R31.3B
N$54  (via drill 0.51)
  Top 0.178: v149.22,103.35 148.91,103.66 142.88,103.66 J3.5
  Bottom 0.178: v149.22,103.35 149.22,104.14 R31.2A
N$55  (via drill 0.51)
  Top 0.178: IC9.16 147.16,114.14 147.16,109.54 150.81,105.89 v150.81,105.09 150.5,104.78 150.5,100.17 148.59,98.27 143.67,98.27 143.51,98.42 143.51,99.38 J3.6
  Bottom 0.178: v150.81,105.09 150.02,105.09 R31.1A
N$56  (via drill 0.51)
  Top 0.178: IC9.82 152.66,136.59 152.07,137.19 152.07,137.97 v151.61,138.43
  Bottom 0.178: v151.61,138.43 152.4,138.43 R35.1A
N$57  (via drill 0.51)
  Top 0.178: v140.18,121.28 142.56,121.28 147.64,116.2 147.64,115.41 IC9.17
  Bottom 0.178: v140.18,121.28 137.16,121.28 136.84,120.97 131.44,120.97 128.75,118.27 130.02,118.27 IC8.3
N$58
  Top 0.178: C60.2 120.17,70.17 120.97,70.17 120.97,71.6 IC11.17
N$59
  Top 0.178: C65.2 128.43,70.17 128.43,71.6 IC11.23
N$60  (via drill 0.51)
  Top 0.178: IC13.3 97.95,66.83 97.95,65.25 R38.2 C67.2 100.97,64.93 101.76,64.93 v102.08,65.25 | v125.89,70.8 125.89,71.6 IC11.21
  Bottom 0.178: v125.89,70.8 120.33,65.25 v102.08,65.25
N$61  (via drill 0.51)
  Top 0.178: v96.84,69.85 IC13.4 | v94.77,69.85 R40.1 C69.1 | v127.16,70.8 127.16,71.6 IC11.22
  Bottom 0.178: v94.77,69.85 v96.84,69.85 96.68,69.53 101.76,64.45 120.81,64.45 v127.16,70.8
N$62  (via drill 0.51)
  Top 0.178: v110.65,48.42 109.86,48.42 R42.1 | v95.57,66.04 95.73,66.2 95.73,66.83 IC13.1 95.73,67.63 93.98,67.63 R40.2 C69.2
  Bottom 0.178: v110.65,48.42 110.65,50.96 v95.57,66.04
N$63
  Top 0.178: C66.2 134.78,193.04 134.78,192.09 IC12.23
N$64  (via drill 0.51)
  Top 0.178: IC14.3 117.63,190.02 117.63,189.39 117.79,189.23 R39.2 C68.2 125.09,189.39 v125.89,189.39 | v133.67,188.59 136.21,188.59 137,189.39 137,190.18 IC12.21
  Bottom 0.178: v133.67,188.59 131.29,188.59 129.86,190.02 126.52,190.02 v125.89,189.39
N$65  (via drill 0.51)
  Top 0.178: C73.1 R41.1 115.57,188.28 117.32,188.28 IC14.4 117.63,188.12 v118.43,188.12 | v135.73,189.39 135.73,190.18 IC12.22
  Bottom 0.178: v135.73,189.39 131.13,189.39 130.02,190.5 120.81,190.5 v118.43,188.12
N$66  (via drill 0.51)
  Top 0.178: v119.54,191.77 119.54,190.98 IC14.1 | v116.36,190.66 115.57,190.66 R41.2 C73.2 112.39,190.66 98.42,190.66 R43.1
  Bottom 0.178: v119.54,191.77 117.47,191.77 v116.36,190.66
N$67  (via drill 0.51)
  Top 0.178: v138.75,110.17 138.75,110.65 140.65,112.55 140.65,114.14 IC9.3
  Bottom 0.178: v138.75,110.17 138.75,110.97 R30.4B
N$68  (via drill 0.51)
  Top 0.178: v140.49,117.16 139.86,117.16 139.38,116.68 139.38,115.73 138.91,115.73 137.64,114.46 v137.64,112.87 130.49,105.73 130.49,79.85 v131.44,78.9 | v133.83,76.52 150.02,60.33 150.02,50.16 161.77,38.42 162.4,38.42 J5.CONDUCTOR
  Bottom 0.178: v137.64,112.87 138.43,112.87 R30.2B | v140.49,117.16 140.49,113.82 R30.1A | v131.44,78.9 v133.83,76.52
N$69
  Top 0.178: R36.2 122.24,69.85 122.24,71.6 IC11.18
N$70  (via drill 0.51)
  Top 0.178: v137.79,188.91 137.79,193.04 137.64,193.04 C62.2 | v141.92,193.04 142.08,192.88 142.08,192.09 IC12.17
  Bottom 0.178: v137.79,188.91 v141.92,193.04
N$71
  Top 0.178: R37.2 142.88,189.71 141.13,189.71 141.13,190.18 IC12.18
N$72  (via drill 0.51)
  Top 0.178: J6.2 R33.2 | v159.38,87.47 IC10.15
  Bottom 0.178: v159.38,87.47 159.38,86.68 161.77,84.3 165.58,84.3 J6.2
N$73  (via drill 0.51)
  Top 0.178: v158.12,87.31 IC10.16
  Bottom 0.178: v158.12,87.31 163.19,82.23 167.8,82.23 167.96,82.39 167.96,83.03 J6.3
N$74
  Top 0.178: R34.2 IC10.11
N$75
  Top 0.178: R33.1 164.47,86.04 165.58,86.04 J6.1
N$76  (via drill 0.51)
  Top 0.178: v147.32,128.59 150.65,131.92 150.65,135.1 IC9.86 | v152.4,108.43 v152.4,110.65 | v155.89,110.01 v162.08,103.82 | v162.08,85.09 158.12,81.12 157.48,81.12 157.48,77.63 152.56,72.71 v147.32,72.71 | v134.94,70.8 134.94,71.6 IC11.28
  Bottom 0.178: v147.32,128.59 147.32,113.51 v152.4,108.43 | v152.4,110.65 155.26,110.65 v155.89,110.01 | v162.08,103.82 v162.08,85.09 | v147.32,72.71 136.84,72.71 v134.94,70.8
N$77  (via drill 0.51)
  Top 0.178: v150.65,145.57 151.13,145.57 154.46,142.24 154.46,141.6 154.15,141.29 154.15,136.53 IC9.79 | v130.33,176.21 v128.27,178.28 | v128.27,189.23 IC12.28
  Bottom 0.178: v150.65,145.57 150.65,155.89 v130.33,176.21 | v128.27,178.28 v128.27,189.23
N$78  (via drill 0.51)
  Top 0.178: v146.3,107.73 141.76,103.19 v141.76,83.82 | v141.76,81.28 141.76,77.15 161.77,57.15 J4.CONDUCTOR
  Bottom 0.178: R30.3A 140.49,111.76 140.49,111.44 R30.4A 140.97,110.97 143.51,110.97 146.3,108.17 v146.3,107.73 | v141.76,81.28 v141.76,83.82
N$79  (via drill 0.51)
  Top 0.178: Q5.1 134.78,140.02 134.78,139.22 135.45,138.56 143,138.56 143.38,138.81 | 143.38,138.81 143.35,138.81 v143.35,138.75 | IC9.100 143.66,138.53 143.38,138.81
  Bottom 0.178: R35.2A 152.4,139.22 143.8,139.22 143.38,138.81 143.35,138.81 v143.35,138.75
N$80
  Top 0.178: C83.1 IC18.3
N$81
  Top 0.178: C84.1 IC19.3
N$82
  Top 0.178: C82.1 78.74,73.98 79.06,74.3 79.53,74.3 79.53,76.36 IC19.2 79.85,77.31 79.85,77.95 80.01,78.11 81.28,78.11 82.23,79.06 82.23,125.41 87.15,130.33 | IC18.2 90.33,136.84 90.33,134.62 89.85,134.62 89.53,134.3 C81.1 89.38,133.35 89.38,132.56 87.15,130.33 | 87.15,130.33 81.6,135.89 74.45,135.89 PWR1.-VOUT
N$83
  Top 0.178: R47.1 118.11,14.45 118.11,15.72 Q6.2 118.11,17.3 118.11,18.1 117.95,18.26 114.3,18.26 113.82,17.78 113.03,17.78 C75.+ 109.54,17.14 | FAN+.TP 109.54,17.14 | 109.54,17.14 109.54,18.57 107.47,20.64 102.08,20.64 100.17,22.54 100.17,23.34 100.33,23.5 R44.1
  pour Top (isolate 0.203): 114.94,24.77 114.94,19.05 122.56,19.05 122.56,24.77
N$84
  Top 0.178: Q6.1 116.05,15.72 116.05,12.22 116.84,12.22 R47.2 R48.1 120.65,11.59 123.83,11.59 125.57,9.84 127,9.84 R49.2
N$85
  Top 0.178: Q7.3 133.99,21.11 143.67,21.11 AUD1.-
N$86
  Top 0.178: C15.1 Q2.2
N$87
  Top 0.178: C14.2 Q1.2
N$88
  Top 0.178: C31.1 Q4.2
N$89
  Top 0.178: Q3.2 C30.2
PHI0  (via drill 0.51)
  Top 0.178: IC9.60 159.54,128.11 161.61,128.11 162.88,129.38 v162.88,140.02 162.88,156.69 139.06,180.5 139.06,183.99 139.22,184.15 142.08,184.15 142.24,183.99 IC12.12 | v121.28,79.69 121.28,80.49 IC11.12
  Bottom 0.178: v121.28,79.69 127.48,73.5 161.29,73.5 173.35,85.57 173.35,129.54 v162.88,140.02
PHI1  (via drill 0.51)
  Top 0.178: v156.37,121.44 155.73,122.08 155.73,128.91 156.53,129.7 157.96,129.7 158.08,129.54 158.27,129.54 IC9.63 | v160.34,127.32 161.45,127.32 161.77,127.64 | 161.77,127.64 164.47,130.33 164.47,157 140.97,180.5 IC12.11 | v122.56,79.69 122.56,80.49 IC11.11 | v159.54,83.66 166.21,90.33 166.21,123.19 161.77,127.64
  Bottom 0.178: v160.34,127.32 159.38,126.36 159.38,121.86 157.54,121.86 157.23,121.54 156.46,121.54 v156.37,121.44 156.37,121.41 156.34,121.41 | v122.56,79.69 125.89,79.69 131.6,73.98 134.62,73.98 140.65,80.01 155.89,80.01 v159.54,83.66
PHI2  (via drill 0.51)
  Top 0.178: v161.61,130.65 160.97,130.02 159.54,130.02 IC9.64 | v163.67,131.92 163.67,156.53 139.7,180.5 IC12.10 | v131.44,76.68 126.84,76.68 123.83,79.69 123.83,80.49 IC11.10 | v161.29,86.52 v159.54,84.77
  Bottom 0.178: 162.4,130.65 v161.61,130.65 | 162.4,130.65 v163.67,131.92 | v131.44,76.68 133.51,74.61 134.62,74.61 140.49,80.49 155.26,80.49 v159.54,84.77 | v161.29,86.52 161.29,110.81 163.99,113.51 163.99,129.06 162.4,130.65
PHI3
  Top 0.178: IC9.65 159.54,130.65 160.46,130.65 161.93,132.11 161.93,139.22 152.56,148.59 152.56,166.37 138.43,180.5 IC12.9 138.43,183.99 137.32,185.1 128.91,185.1 122.08,178.28 116.84,178.28 111.44,172.88 111.44,156.69 113.82,154.31 113.82,146.05 121.6,138.27 121.6,130.02 121.13,129.54 121.13,105.09 124.62,101.6 124.62,82.55 IC11.9
PHI4  (via drill 0.51)
  Top 0.178: v152.56,131.6 158.27,131.6 IC9.67 | v140.3,129.67 140.68,129.92 140.68,132.33 v140.3,132.46 | v131.13,127.48 126.21,122.56 126.21,82.55 IC11.8 | v137.16,171.93 137.16,162.56 v132.08,157.48 | v137.16,176.85 IC12.8
  Bottom 0.178: 135.73,132.08 138.68,132.08 139.06,132.46 v140.3,132.46 | v131.13,127.48 135.73,132.08 | v137.16,171.93 v137.16,176.85 | v132.08,157.48 132.08,135.73 135.73,132.08 | v140.3,129.67 143.13,129.67 145.16,131.7 152.4,131.7 152.53,131.57 152.56,131.57 v152.56,131.6
PHI5  (via drill 0.51)
  Top 0.178: 160.81,136.68 160.81,139.7 152.08,148.43 152.08,160.81 135.89,177.01 IC12.7 | 160.81,136.68 160.81,133.62 159.75,132.56 159.54,132.56 IC9.69 | v127.64,79.69 127.64,80.49 IC11.7 | v137,79.69 140.49,79.69 v140.97,79.22 | v161.13,136.68 160.81,136.68
  Bottom 0.178: v137,79.69 v127.64,79.69 | v140.97,79.22 156.37,79.22 158.91,81.76 168.91,81.76 170.02,82.87 170.02,88.9 167,91.92 167,130.81 v161.13,136.68
PHI6  (via drill 0.51)
  Top 0.178: v160.02,135.57 160.02,133.36 159.73,133.07 IC9.70 | v158.59,156.53 v158.59,149.38 | v134.46,180.5 134.46,181.29 IC12.6 | v128.59,99.85 128.59,82.55 IC11.6 | v121.92,106.52 121.92,126.68 121.76,126.84 121.76,129.54 122.08,129.86 122.08,138.43 120.49,140.02 v120.49,157.64
  Bottom 0.178: v160.02,135.57 158.59,137 v158.59,149.38 | v158.59,156.53 134.62,180.5 v134.46,180.5 134.14,180.82 133.67,181.29 133.03,181.29 120.49,168.75 v120.49,157.64 | v121.92,106.52 v128.59,99.85
PHI7  (via drill 0.51)
  Top 0.178: v157.32,132.4 157.32,133.35 157.48,133.51 158.27,133.51 IC9.71 | v133.35,180.5 IC12.5 | v128.75,131.6 125.73,128.59 125.73,108.27 125.41,107.95 125.41,79.85 126.36,78.9 128.91,78.9 129.7,79.69 129.7,80.49 IC11.5 | v130.65,146.84 v145.73,161.93
  Bottom 0.178: v157.32,132.4 156.21,131.29 156.21,130.33 156.53,130.02 159.38,130.02 159.38,135.1 157.8,136.68 157.8,150.18 145.89,162.08 | 145.89,162.08 133.35,174.62 v133.35,180.5 | v128.75,131.6 130.65,133.51 v130.65,146.84 | v145.73,161.93 145.89,162.08 | 145.89,162.08
PHI8  (via drill 0.51)
  Top 0.178: v155.73,132.4 157.32,133.99 158.27,133.99 IC9.72 | v155.89,105.89 v155.89,108.9 | v150.18,94.93 142.56,87.31 142.56,83.5 142.08,83.03 135.73,83.03 134.62,84.14 132.08,84.14 131.29,83.34 131.29,82.55 IC11.4 | v134.14,178.44 132.24,180.34 132.24,181.29 IC12.4 | v134.14,160.66 v134.14,174.94 | 137.76,136.05 v137.64,136.05 137.79,136.05 137.79,136.02 139.32,134.49 140.08,134.49 144.62,129.95 v144.62,129.38
  Bottom 0.178: 155.73,129.38 155.73,123.19 147.96,115.41 147.96,113.54 152.15,109.35 152.65,109.35 153.03,108.97 153.03,108.9 v155.89,108.9 | 155.73,129.38 v155.73,132.4 | v155.89,105.89 150.18,100.17 v150.18,94.93 | v134.14,174.94 v134.14,178.44 | v134.14,160.66 140.4,154.4 140.4,148.81 137.64,146.05 v137.64,136.05 | 155.73,129.38 v144.62,129.38
PHI9  (via drill 0.51)
  Top 0.178: 143.03,167.32 130.81,179.55 IC12.3 | 143.03,167.32 150.65,159.7 150.65,147 157.16,140.49 157.16,136.53 IC9.73 | v132.4,83.34 132.4,82.55 IC11.3 | v123.67,108.27 123.67,109.06 123.51,109.22 123.51,120.97 124.62,122.08 124.62,136.53 121.6,139.54 v121.6,147.16 | v127.79,153.35 129.06,153.35 143.03,167.32
  Bottom 0.178: v132.4,83.34 132.4,99.54 v123.67,108.27 | v121.6,147.16 v127.79,153.35
PHI10  (via drill 0.51)
  Top 0.178: v155.89,140.34 156.69,139.54 156.69,136.53 IC9.74 | v155.89,142.88 155.89,143.35 151.13,148.11 151.13,160.34 v132.24,179.23 | v132.24,179.23 131.44,180.02 131.44,183.99 131.29,184.15 129.7,184.15 129.54,183.99 IC12.2 | v133.67,83.34 133.67,82.55 IC11.2 | v124.78,108.43 124.78,108.9 125.09,109.22 125.09,136.68 122.4,139.38 v122.4,152.72 | v132.24,179.23
  Bottom 0.178: v155.89,142.88 v155.89,140.34 | v133.67,83.34 133.67,99.54 v124.78,108.43 | v122.4,152.72 122.4,158.59 120.97,160.02 120.97,167.96 v132.24,179.23
PHI11  (via drill 0.51)
  Top 0.178: 158.75,136.68 158.75,141.13 151.61,148.27 151.61,160.66 135.25,177.01 135.25,183.99 134.62,184.63 129.06,184.63 128.43,183.99 128.43,183.2 IC12.1 | 158.75,136.68 158.75,134.78 156.21,134.78 156.21,135.1 IC9.75 | v136.68,81.76 135.25,81.76 IC11.1 | v139.06,81.76 141.13,81.76 141.45,82.07 155.73,82.07 161.45,87.79 162.56,87.79 165.42,90.65 v165.42,122.87 | v160.02,136.68 158.75,136.68
  Bottom 0.178: v139.06,81.76 v136.68,81.76 | v165.42,122.87 165.42,131.29 v160.02,136.68
PHI-X
  Top 0.178: R42.2 107.16,48.26 105.09,48.26 104.93,48.42 104.46,48.42 104.46,49.21 104.3,49.21 IC2.3
PHI-Y  (via drill 0.51)
  Top 0.178: v99.22,188.75 98.42,188.75 R43.2 | v97.79,184.31 IC5.3
  Bottom 0.178: v99.22,188.75 99.22,185.74 v97.79,184.31
USB0  (via drill 0.51)
  Top 0.178: v149.22,83.34 151.76,83.34 156.21,87.79 156.21,91.28 164.94,100.01 164.94,116.84 161.77,120.02 159.54,120.02 IC9.44 | v148.27,81.28 148.11,81.12 148.11,80.33 IC10.1
  Bottom 0.178: v149.22,83.34 149.22,82.23 v148.27,81.28
USB1  (via drill 0.51)
  Top 0.178: v155.42,92.39 164.47,101.44 164.47,116.68 161.61,119.54 159.54,119.54 IC9.43 | v149.38,81.28 149.22,81.12 IC10.2
  Bottom 0.178: v155.42,92.39 155.42,93.5 154.94,93.98 154.31,93.98 153.67,93.34 153.67,92.87 150.02,89.22 150.02,81.92 v149.38,81.28
USB2  (via drill 0.51)
  Top 0.178: v154.62,93.19 163.99,102.55 163.99,116.52 161.45,119.06 159.54,119.06 IC9.42 | v150.65,81.28 150.5,81.12 IC10.3
  Bottom 0.178: v154.62,93.19 150.65,89.22 v150.65,81.28
USB3  (via drill 0.51)
  Top 0.178: v163.19,113.82 163.51,114.14 163.51,116.36 161.29,118.59 159.54,118.59 IC9.41 | v157,85.41 155.07,83.31 v153.03,83.34 | v151.92,81.28 151.76,81.12 IC10.4
  Bottom 0.178: v163.19,113.82 163.19,113.35 157,107.16 v157,85.41 | v153.03,83.34 153.03,82.39 v151.92,81.28
USB4  (via drill 0.51)
  Top 0.178: v162.72,114.94 162.72,116.52 161.13,118.11 159.54,118.11 IC9.40 | v149.38,93.03 147.96,91.6 IC10.24
  Bottom 0.178: v162.72,114.94 162.72,114.46 162.4,114.14 162.4,113.51 149.38,100.49 v149.38,93.03
USB5  (via drill 0.51)
  Top 0.178: v155.42,97.95 155.1,98.27 155.1,114.14 IC9.32 | v149.22,91.76 IC10.23
  Bottom 0.178: v155.42,97.95 v149.22,91.76
USB6  (via drill 0.51)
  Top 0.178: v154.94,96.36 154.62,96.68 154.62,114.14 IC9.31 | v150.5,91.92 IC10.22
  Bottom 0.178: v154.94,96.36 v150.5,91.92
USB7  (via drill 0.51)
  Top 0.178: v152.88,93.19 154.15,94.46 154.15,114.14 IC9.30 | v151.76,92.08 IC10.21
  Bottom 0.178: v152.88,93.19 v151.76,92.08
USB8  (via drill 0.51)
  Top 0.178: v156.21,99.38 156.21,95.89 153.83,93.5 v153.83,91.28 | v153.19,81.28 153.03,81.12 IC10.5 | IC9.28 153.19,114.14 153.19,113.96 153.67,113.49 153.67,102.49 153.42,102.23 v153.35,102.23
  Bottom 0.178: v156.21,99.38 v153.35,102.23 | v153.83,91.28 153.83,81.92 v153.19,81.28
USB9
  Top 0.178: IC9.25 151.61,114.14 151.61,93.34 153.03,91.92 IC10.20
USB10  (via drill 0.51)
  Top 0.178: v150.81,107 151.13,107.31 151.13,114.14 IC9.24 | v152.4,106.68 152.4,102.08 v153.35,101.12 | v154.46,81.28 154.31,81.12 IC10.6
  Bottom 0.178: v152.4,106.68 152.08,107 v150.81,107 | v153.35,101.12 156.21,98.27 156.21,83.03 v154.46,81.28

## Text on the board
Top: Coil Y | +4V Monitor | + Com | - Com | -4V Monitor | + - | 5V | Coil X | TOP Coil Quardature Driver, J.Thywissen Lab Rev:A | University of Toronto, Physics Dept., Quantum Optics
Document: Quadrature Driver | A.Stummer 2007 | A | 0.007" | 0.025" | 0.007" | 0.00625" | 0.025" | "Autorouter Normal Setup.ctl"
bDocu: TOP Coil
